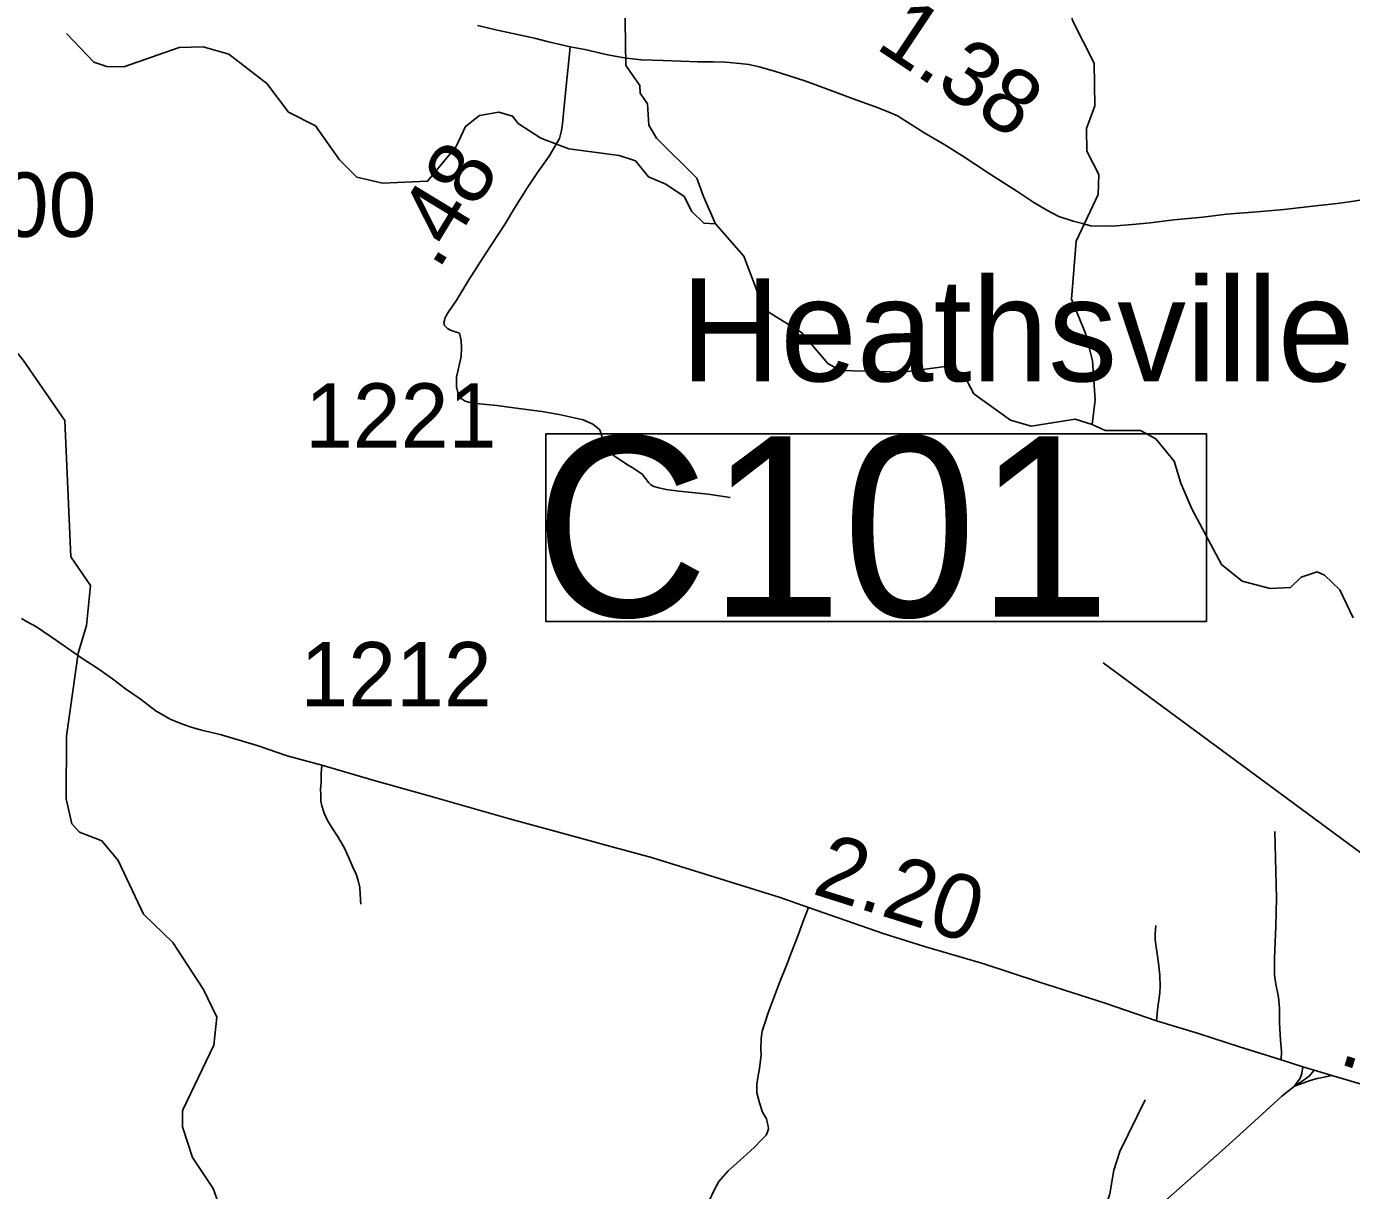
# Model space of a CAD drawing. Extents: x 2290615 to 2522933, y 819489 to 1012715.
# Drawn here: x 2353015 to 2363308, y 911481 to 920524 of the extents above; entities that cross this region are included whole.
import ezdxf

# ---------------------------------------------------------------- set-up
doc = ezdxf.new("R2010")
doc.units = 0
for name, color, linetype in [('Exist Civil Demographics City Label', 7, 'Continuous'), ('Exist Hydrographic Creek Single Shore', 7, 'Continuous'), ('Exist Hydrographic Misc Water Feature', 7, 'Continuous'), ('Exist Road Non-System Type 51', 7, 'Continuous'), ('Exist Road Primary NC Attributed', 7, 'Continuous'), ('Exist Road Primary NC Mileage Hundredths English Label', 7, 'Continuous'), ('Exist Road Secondary Mileage Hundredths English Label', 7, 'Continuous'), ('Exist Road Secondary Structure Culvert Number Label', 7, 'Continuous'), ('Exist Road Secondary Type 20 Attributed', 7, 'Continuous'), ('Exist Road Secondary Type 51 Attributed', 7, 'Continuous'), ('Exist Road Secondary Type 51 Number Label', 7, 'Continuous')]:
    doc.layers.add(name, color=color, linetype=linetype)

msp = doc.modelspace()

# ---------------------------------------------------------------- linework, layer by layer
at = {"layer": 'Exist Hydrographic Creek Single Shore'}
for points in [[(2358368, 918990), (2358274, 919203), (2358222, 919346), (2357910, 919658), (2357850, 919757), (2357840, 919924), (2357781, 920007), (2357780, 920066), (2357670, 920222), (2357664, 920737), (2357578, 920895)], [(2361294, 917433), (2361160, 917474), (2360819, 917420), (2360660, 917466), (2360375, 917671), (2360298, 917812), (2360189, 917887), (2359823, 917839), (2359339, 917852), (2359239, 917907), (2359036, 918148), (2358784, 918302), (2358725, 918378), (2358587, 918740), (2358368, 918990)], [(2363320, 915931), (2363217, 916147), (2363099, 916263), (2363041, 916287), (2362916, 916246), (2362834, 916167), (2362676, 916157), (2362458, 916214), (2362298, 916345), (2362068, 916776), (2361982, 916976), (2361930, 917147), (2361787, 917322), (2361669, 917386), (2361394, 917385), (2361294, 917433)]]:
    msp.add_lwpolyline(points, dxfattribs=at)
at = {"layer": 'Exist Hydrographic Misc Water Feature'}
for points in [[(2361294, 917433), (2361317, 917624), (2361296, 917926), (2361244, 918134), (2361132, 918405), (2361169, 918856), (2361339, 919218), (2361346, 919375), (2361252, 919555), (2361250, 919732), (2361314, 919909), (2361310, 920240), (2361140, 920571), (2361087, 920845), (2361124, 921181), (2361173, 921282), (2361313, 921422), (2361344, 921624), (2361317, 921747), (2361546, 922134), (2361852, 922288), (2362009, 922422), (2362173, 922643), (2362289, 922710)], [(2358368, 918990), (2358276, 918997), (2358183, 919088), (2358124, 919204), (2357981, 919300), (2357847, 919356), (2357745, 919480), (2357620, 919521), (2357228, 919574), (2357010, 919657), (2356834, 919771), (2356791, 919828), (2356683, 919860), (2356533, 919834), (2356426, 919748), (2356353, 919591), (2356131, 919322), (2355781, 919308), (2355581, 919355), (2355446, 919488), (2355259, 919752), (2355050, 919859), (2354881, 920082), (2354586, 920309), (2354386, 920367), (2354202, 920362), (2353771, 920210), (2353638, 920214), (2353537, 920246), (2353326, 920471)], [(2354226, 912098), (2354233, 912113), (2354470, 912610), (2354493, 912828), (2354390, 913043), (2354152, 913408), (2353925, 913628), (2353728, 914044), (2353601, 914199), (2353426, 914264), (2353367, 914331), (2353323, 914523), (2353325, 915012), (2353417, 915656), (2353481, 915872), (2353511, 916182), (2353358, 916405), (2353312, 917463), (2352990, 917933), (2352796, 918171), (2352735, 918388), (2352558, 918562), (2352507, 918635)], [(2360838, 906631), (2360928, 906776), (2361105, 907296), (2361209, 907713), (2361200, 908396), (2361273, 909256), (2361465, 909949), (2361488, 910108), (2361442, 910480), (2361356, 910703), (2361346, 910788), (2361321, 910797), (2361286, 910963), (2361390, 911332), (2361430, 911455), (2361461, 911640), (2361509, 911783), (2361705, 912185)], [(2354542, 911280), (2354465, 911497), (2354304, 911737), (2354226, 911977), (2354226, 912098)]]:
    msp.add_lwpolyline(points, dxfattribs=at)
at = {"layer": 'Exist Road Non-System Type 51'}
for points in [[(2358481, 916865), (2358310, 916892), (2358082, 916915), (2357984, 916926), (2357926, 916941), (2357889, 916950), (2357866, 916963), (2357850, 916978), (2357798, 917047), (2357732, 917090), (2357676, 917125), (2357573, 917195), (2357538, 917225), (2357519, 917247), (2357488, 917333), (2357468, 917390), (2357437, 917416), (2357415, 917434), (2357338, 917468), (2357152, 917510), (2357017, 917533), (2356800, 917561), (2356668, 917579), (2356479, 917599), (2356423, 917614), (2356391, 917634), (2356371, 917659), (2356356, 917725), (2356356, 917800), (2356391, 917960), (2356394, 918027), (2356392, 918083), (2356382, 918133), (2356373, 918145)], [(2355308, 914785), (2355305, 914722), (2355305, 914651), (2355300, 914600), (2355302, 914557), (2355302, 914506), (2355308, 914469), (2355328, 914413), (2355354, 914357), (2355387, 914302), (2355430, 914233), (2355483, 914145), (2355519, 914065), (2355549, 913992), (2355575, 913938), (2355592, 913890), (2355605, 913836), (2355610, 913739), (2355612, 913705)], [(2362712, 914270), (2362726, 913752), (2362720, 913534), (2362711, 913284), (2362711, 913155), (2362720, 913083), (2362741, 912984), (2362748, 912899), (2362749, 912782), (2362757, 912649), (2362763, 912560), (2362761, 912497)], [(2359089, 913679), (2359049, 913573), (2359010, 913464), (2358958, 913332), (2358921, 913236), (2358863, 913089), (2358777, 912862), (2358751, 912780), (2358729, 912720), (2358721, 912661), (2358720, 912580), (2358723, 912534), (2358708, 912429), (2358696, 912358), (2358688, 912307), (2358689, 912240), (2358710, 912162), (2358732, 912090), (2358763, 912038), (2358769, 912018), (2358772, 912002), (2358776, 911980), (2358780, 911960), (2358770, 911938), (2358761, 911912), (2358723, 911872), (2358670, 911817), (2358555, 911714), (2358466, 911633), (2358393, 911550), (2358356, 911483), (2358319, 911401)], [(2361787, 913539), (2361784, 913478), (2361782, 913429), (2361809, 913247), (2361819, 913152), (2361822, 913068), (2361820, 913016), (2361810, 912959), (2361800, 912886), (2361792, 912799)], [(2362930, 912442), (2362921, 912393), (2362917, 912375), (2362907, 912349), (2362887, 912323), (2362866, 912291), (2362995, 912338), (2363040, 912352), (2363082, 912359), (2363156, 912374)]]:
    msp.add_lwpolyline(points, dxfattribs=at)
at = {"layer": 'Exist Road Primary NC Attributed'}
for points in [[(2356519, 920533), (2356684, 920494), (2356961, 920433), (2357069, 920404), (2357238, 920367)], [(2357238, 920367), (2357351, 920345), (2357518, 920306), (2357586, 920294), (2357675, 920278), (2357793, 920265), (2357962, 920260), (2358097, 920255), (2358229, 920251), (2358349, 920250), (2358445, 920246), (2358555, 920237), (2358627, 920230), (2358707, 920211), (2358826, 920178), (2359061, 920103), (2359278, 920022), (2359437, 919963), (2359611, 919901), (2359709, 919862), (2359781, 919830), (2359994, 919696), (2360150, 919606), (2360282, 919521), (2360500, 919376), (2360707, 919245), (2360840, 919156), (2360940, 919098), (2361034, 919047), (2361146, 919011), (2361219, 918994), (2361280, 918977), (2361386, 918973), (2361481, 918976), (2361607, 918985), (2361744, 918998), (2361927, 919023), (2362154, 919044), (2362337, 919066), (2362574, 919084), (2362782, 919103), (2363051, 919133), (2363176, 919147), (2363293, 919161), (2363407, 919179)]]:
    msp.add_lwpolyline(points, dxfattribs=at)
at = {"layer": 'Exist Road Secondary Structure Culvert Number Label'}
msp.add_lwpolyline([(2357050, 917361), (2362181, 917361), (2362181, 915901), (2357050, 915901)], close=True, dxfattribs=at)
msp.add_lwpolyline([(2365414, 914105), (2363380, 914105), (2361379, 915581)], dxfattribs=at)
at = {"layer": 'Exist Road Secondary Type 20 Attributed'}
msp.add_lwpolyline([(2357238, 920367), (2357227, 920259), (2357208, 920061), (2357188, 919876), (2357179, 919768), (2357170, 919716), (2357155, 919655), (2357076, 919517), (2356985, 919389), (2356906, 919273), (2356806, 919112), (2356733, 918992), (2356581, 918757), (2356452, 918556), (2356352, 918393), (2356293, 918308), (2356267, 918264), (2356262, 918240), (2356258, 918226), (2356262, 918202), (2356272, 918190), (2356286, 918178), (2356308, 918164), (2356338, 918155), (2356373, 918145)], dxfattribs=at)
at = {"layer": 'Exist Road Secondary Type 51 Attributed'}
for points in [[(2352975, 915926), (2353021, 915898), (2353092, 915860), (2353248, 915754), (2353444, 915616), (2353570, 915536), (2353683, 915456), (2353784, 915379), (2353897, 915300), (2354023, 915204), (2354135, 915141), (2354235, 915102), (2354293, 915080), (2354374, 915057), (2354520, 915024), (2354806, 914938), (2355041, 914858), (2355308, 914785), (2355715, 914666), (2356132, 914549), (2356768, 914369), (2357262, 914233), (2357554, 914154), (2357870, 914068), (2358171, 913976), (2358520, 913866), (2358869, 913758), (2359089, 913679), (2359669, 913479), (2359992, 913377), (2360445, 913246), (2360877, 913103), (2361394, 912936), (2361792, 912799), (2362119, 912702), (2362438, 912598), (2362761, 912497), (2362930, 912442), (2363017, 912415)], [(2363017, 912415), (2362979, 912370), (2362941, 912342), (2362866, 912291), (2362767, 912214), (2362523, 911991), (2362302, 911791), (2362039, 911559), (2361835, 911377)], [(2363017, 912415), (2363156, 912374), (2363596, 912244), (2363997, 912117), (2364237, 912042), (2364448, 911979), (2364611, 911928), (2364727, 911896)]]:
    msp.add_lwpolyline(points, dxfattribs=at)

# ---------------------------------------------------------------- texts
at = {"layer": 'Exist Civil Demographics City Label'}
msp.add_text('Heathsville', height=800, rotation=360, dxfattribs=at).set_placement((2358098, 917768))
at = {"layer": 'Exist Road Primary NC Mileage Hundredths English Label'}
msp.add_text('1.38', height=500, rotation=326.2905, dxfattribs=at).set_placement((2359599, 920361))
at = {"layer": 'Exist Road Secondary Mileage Hundredths English Label'}
for s, rotation, p in [('.48', 58.6902, (2356214, 918624)), ('2.20', 342.4343, (2359108, 913790)), ('.34', 342.3892, (2363195, 912470))]:
    msp.add_text(s, height=500, rotation=rotation, dxfattribs=at).set_placement(p)
at = {"layer": 'Exist Road Secondary Structure Culvert Number Label'}
msp.add_text('C101', height=1400, dxfattribs=at).set_placement((2356961, 915940))
at = {"layer": 'Exist Road Secondary Type 51 Number Label'}
for s, p in [('1200', (2352071, 918890)), ('1221', (2355178, 917252)), ('1212', (2355142, 915242))]:
    msp.add_text(s, height=500, rotation=360, dxfattribs=at).set_placement(p)

doc.saveas('drawing.dxf')
